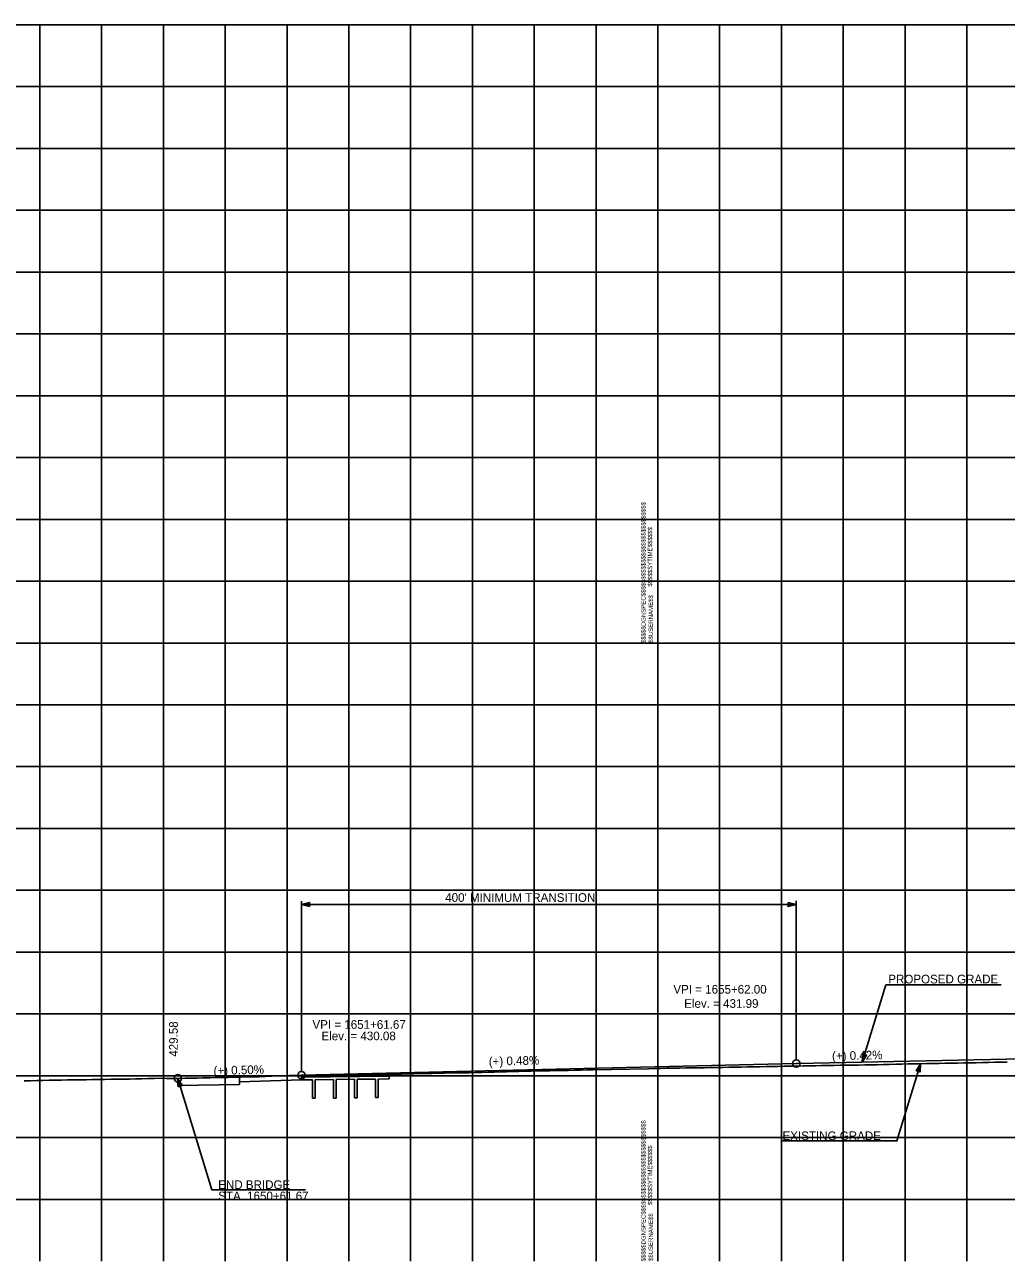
# Model space of a CAD drawing. Extents: x -90830 to 2015517, y -20856 to 836331.
# Drawn here: x 53861 to 54655, y -9797 to -8797 of the extents above; entities that cross this region are included whole.
import ezdxf

# ---------------------------------------------------------------- set-up
doc = ezdxf.new("R2010")
doc.units = 0
for name, color, linetype in [('Level 1', 7, 'Continuous'), ('RD_DDB_GradeTX', 7, 'Continuous'), ('RD_DDB_Profile_EX', 7, 'Continuous'), ('RD_DDB_Profile_Lbl', 7, 'Continuous'), ('RD_DDB_Profile_PR', 7, 'Continuous'), ('RD_DDB_VCLbl', 7, 'Continuous'), ('RD_PD_Final_TX', 7, 'Continuous')]:
    doc.layers.add(name, color=color, linetype=linetype)

msp = doc.modelspace()

# ---------------------------------------------------------------- linework, layer by layer
at = {"layer": 'Level 1'}
for p, q in [((52773.46, -8797.12), (54373.46, -8797.12)), ((53873.46, -8797.12), (53873.46, -9297.12)), ((53923.46, -8797.12), (53923.46, -9297.12)), ((53973.46, -8797.12), (53973.46, -9297.12)), ((54023.46, -8797.12), (54023.46, -9297.12)), ((54073.46, -8797.12), (54073.46, -9297.12)), ((54123.46, -8797.12), (54123.46, -9297.12)), ((54173.46, -8797.12), (54173.46, -9297.12)), ((54223.46, -8797.12), (54223.46, -9297.12)), ((54273.46, -8797.12), (54273.46, -9297.12)), ((54323.46, -8797.12), (54323.46, -9297.12)), ((54373.46, -8797.12), (54373.46, -9297.12)), ((54373.46, -8797.12), (54373.46, -9297.12)), ((54373.46, -8797.12), (55973.46, -8797.12)), ((54373.46, -8797.12), (54373.46, -9297.12)), ((54423.46, -8797.12), (54423.46, -9297.12)), ((54473.46, -8797.12), (54473.46, -9297.12)), ((54523.46, -8797.12), (54523.46, -9297.12)), ((54573.46, -8797.12), (54573.46, -9297.12)), ((54623.46, -8797.12), (54623.46, -9297.12)), ((52773.46, -8847.12), (54373.46, -8847.12)), ((54373.46, -8847.12), (55973.46, -8847.12)), ((52773.46, -8897.12), (54373.46, -8897.12)), ((54373.46, -8897.12), (55973.46, -8897.12)), ((52773.46, -8947.12), (54373.46, -8947.12)), ((54373.46, -8947.12), (55973.46, -8947.12)), ((52773.46, -8997.12), (54373.46, -8997.12)), ((54373.46, -8997.12), (55973.46, -8997.12)), ((52773.46, -9047.12), (54373.46, -9047.12)), ((54373.46, -9047.12), (55973.46, -9047.12)), ((52773.46, -9097.12), (54373.46, -9097.12)), ((54373.46, -9097.12), (55973.46, -9097.12)), ((52773.46, -9147.12), (54373.46, -9147.12)), ((54373.46, -9147.12), (55973.46, -9147.12)), ((52773.46, -9197.12), (54373.46, -9197.12)), ((54373.46, -9197.12), (55973.46, -9197.12)), ((52773.46, -9247.12), (54373.46, -9247.12)), ((54373.46, -9247.12), (55973.46, -9247.12)), ((52773.46, -9297.12), (54373.46, -9297.12)), ((52773.46, -9297.12), (54373.46, -9297.12)), ((53873.46, -9297.12), (53873.46, -9797.12)), ((53923.46, -9297.12), (53923.46, -9797.12)), ((53973.46, -9297.12), (53973.46, -9797.12)), ((54023.46, -9297.12), (54023.46, -9797.12)), ((54073.46, -9297.12), (54073.46, -9797.12)), ((54123.46, -9297.12), (54123.46, -9797.12)), ((54173.46, -9297.12), (54173.46, -9797.12)), ((54223.46, -9297.12), (54223.46, -9797.12)), ((54273.46, -9297.12), (54273.46, -9797.12)), ((54323.46, -9297.12), (54323.46, -9797.12)), ((54373.46, -9297.12), (54373.46, -9797.12)), ((54373.46, -9297.12), (54373.46, -9797.12)), ((54373.46, -9297.12), (55973.46, -9297.12)), ((54373.46, -9297.12), (55973.46, -9297.12)), ((54373.46, -9297.12), (54373.46, -9797.12)), ((54423.46, -9297.12), (54423.46, -9797.12)), ((54473.46, -9297.12), (54473.46, -9797.12)), ((54523.46, -9297.12), (54523.46, -9797.12)), ((54573.46, -9297.12), (54573.46, -9797.12)), ((54623.46, -9297.12), (54623.46, -9797.12)), ((52773.46, -9347.12), (54373.46, -9347.12)), ((54373.46, -9347.12), (55973.46, -9347.12)), ((52773.46, -9397.12), (54373.46, -9397.12)), ((54373.46, -9397.12), (55973.46, -9397.12)), ((52773.46, -9447.12), (54373.46, -9447.12)), ((54373.46, -9447.12), (55973.46, -9447.12)), ((52773.46, -9497.12), (54373.46, -9497.12)), ((54373.46, -9497.12), (55973.46, -9497.12)), ((52773.46, -9547.12), (54373.46, -9547.12)), ((54373.46, -9547.12), (55973.46, -9547.12)), ((52773.46, -9597.12), (54373.46, -9597.12)), ((54373.46, -9597.12), (55973.46, -9597.12)), ((52773.46, -9647.12), (54373.46, -9647.12)), ((54373.46, -9647.12), (55973.46, -9647.12)), ((52773.46, -9697.12), (54373.46, -9697.12)), ((54373.46, -9697.12), (55973.46, -9697.12)), ((52773.46, -9747.12), (54373.46, -9747.12)), ((54373.46, -9747.12), (55973.46, -9747.12))]:
    msp.add_line(p, q, dxfattribs=at)
at = {"layer": 'RD_DDB_GradeTX'}
for centre in [(54485.46, -9637.16), (53985.13, -9649.21), (54085.13, -9646.7)]:
    msp.add_circle(centre, 3, dxfattribs=at)
at = {"layer": 'RD_DDB_Profile_EX'}
for points in [[(54420.95, -9640.42), (54425.95, -9640.33), (54430.95, -9640.24), (54435.95, -9640.13), (54440.95, -9640.03), (54445.95, -9639.92), (54450.95, -9639.83), (54455.95, -9639.75), (54460.95, -9639.67), (54465.95, -9639.59), (54470.95, -9639.51), (54475.95, -9639.42), (54480.95, -9639.33), (54485.95, -9639.24), (54490.95, -9639.15), (54495.95, -9639.06), (54500.95, -9638.97), (54505.95, -9638.88), (54510.95, -9638.8), (54515.95, -9638.73), (54520.95, -9638.66), (54525.95, -9638.59), (54530.95, -9638.52), (54535.95, -9638.45), (54540.95, -9638.39), (54545.95, -9638.33), (54550.95, -9638.23), (54555.95, -9638.08), (54560.95, -9637.93), (54565.95, -9637.78), (54570.95, -9637.65), (54575.95, -9637.55), (54580.95, -9637.46), (54585.95, -9637.36), (54590.95, -9637.27), (54595.95, -9637.19), (54600.95, -9637.11), (54605.95, -9637.04), (54610.95, -9636.95), (54615.95, -9636.84), (54620.95, -9636.74), (54625.95, -9636.65), (54630.95, -9636.55), (54635.95, -9636.44), (54640.95, -9636.34), (54645.95, -9636.23), (54650.95, -9636.13), (54655.95, -9636.04)], [(53920.95, -9650.1), (53925.95, -9650.02), (53930.95, -9649.94), (53935.95, -9649.87), (53940.95, -9649.8), (53945.95, -9649.72), (53950.95, -9649.63), (53955.95, -9649.5), (53960.95, -9649.37), (53965.95, -9649.23), (53970.95, -9649.16), (53975.95, -9649.18), (53980.95, -9649.19), (53985.95, -9649.21), (53990.95, -9649.17), (53995.95, -9649.07), (54000.95, -9648.96), (54005.95, -9648.85), (54010.95, -9648.74), (54015.95, -9648.63), (54020.95, -9648.51), (54025.95, -9648.4), (54030.95, -9648.28), (54035.95, -9648.18), (54040.95, -9648.07), (54045.95, -9647.97), (54050.95, -9647.83), (54055.95, -9647.64), (54060.95, -9647.45), (54065.95, -9647.25), (54070.95, -9647.08), (54075.95, -9646.95), (54080.95, -9646.81), (54085.95, -9646.68), (54090.95, -9646.58), (54095.95, -9646.55), (54100.95, -9646.5), (54105.95, -9646.46), (54110.95, -9646.42), (54115.95, -9646.38), (54120.95, -9646.34), (54125.95, -9646.3), (54130.95, -9646.24), (54135.95, -9646.17), (54140.95, -9646.11), (54145.95, -9646.04), (54150.95, -9645.96), (54155.95, -9645.87), (54160.95, -9645.77), (54165.95, -9645.68), (54170.95, -9645.57), (54175.95, -9645.47), (54180.95, -9645.36), (54185.95, -9645.25), (54190.95, -9645.15), (54195.95, -9645.05), (54200.95, -9644.95), (54205.95, -9644.85), (54210.95, -9644.76), (54215.95, -9644.68), (54220.95, -9644.6), (54225.95, -9644.52), (54230.95, -9644.41), (54235.95, -9644.26), (54240.95, -9644.11), (54245.95, -9643.95), (54250.95, -9643.81), (54255.95, -9643.67), (54260.95, -9643.53), (54265.95, -9643.4), (54270.95, -9643.28), (54275.95, -9643.18), (54280.95, -9643.09), (54285.95, -9643), (54290.95, -9642.9), (54295.95, -9642.82), (54300.95, -9642.73), (54305.95, -9642.65), (54310.95, -9642.55), (54315.95, -9642.43), (54320.95, -9642.32), (54365.95, -9641.41), (54370.95, -9641.29), (54375.95, -9641.18), (54380.95, -9641.07), (54385.95, -9640.96), (54390.95, -9640.87), (54395.95, -9640.8), (54400.95, -9640.73), (54405.95, -9640.66), (54410.95, -9640.59), (54415.95, -9640.5), (54420.95, -9640.42)], [(53860.95, -9651.19), (53865.95, -9651.09), (53870.95, -9650.98), (53875.95, -9650.86), (53880.95, -9650.74), (53885.95, -9650.63), (53890.95, -9650.53), (53895.95, -9650.46), (53900.95, -9650.39), (53905.95, -9650.33), (53910.95, -9650.26), (53915.95, -9650.18), (53920.95, -9650.1)]]:
    msp.add_lwpolyline(points, dxfattribs=at)
at = {"layer": 'RD_DDB_Profile_PR'}
for p, q in [((54486.46, -9637.14), (54668.46, -9633.33)), ((53985.13, -9649.21), (54085.13, -9646.7))]:
    msp.add_line(p, q, dxfattribs=at)
msp.add_lwpolyline([(53985.13, -9649.21), (54085.13, -9646.7), (54485.46, -9637.16), (54486.46, -9637.14)], dxfattribs=at)
at = {"layer": 'RD_DDB_VCLbl'}
for p, q in [((54085.16, -9505.77), (54085.16, -9642.98)), ((54085.16, -9508.59), (54485.46, -9508.59)), ((54485.46, -9505.63), (54485.46, -9634.52))]:
    msp.add_line(p, q, dxfattribs=at)
at = {"layer": 'RD_PD_Final_TX'}
for p, q in [((54538.86, -9636.04), (54557.91, -9573.67)), ((54557.91, -9573.67), (54651.3, -9573.67)), ((54538.86, -9636.04), (54539.2, -9629.37)), ((54540.75, -9629.85), (54538.86, -9636.04)), ((54539.2, -9629.37), (54542.3, -9630.32)), ((54538.86, -9636.04), (54542.3, -9630.32)), ((54585.95, -9637.36), (54582.51, -9643.09)), ((54584.06, -9643.56), (54585.95, -9637.36)), ((54585.95, -9637.36), (54585.61, -9644.03)), ((53985.13, -9649.21), (53985.13, -9655.04)), ((54035.13, -9648.2), (54085.13, -9646.7)), ((54035.13, -9654.03), (54035.13, -9648.2)), ((54035.13, -9648.2), (54035.13, -9651.95)), ((54085.13, -9646.7), (54156.13, -9645.86)), ((54085.13, -9650.45), (54085.13, -9646.7)), ((54085.13, -9648.34), (54156.13, -9647.5)), ((54113.13, -9650.12), (54128.13, -9649.94)), ((54128.13, -9649.94), (54128.13, -9664.93)), ((54130.13, -9649.92), (54145.13, -9649.74)), ((54130.13, -9649.92), (54130.13, -9664.93)), ((54145.13, -9649.74), (54145.13, -9664.73)), ((54147.13, -9649.72), (54156.13, -9649.61)), ((54147.13, -9649.72), (54147.13, -9664.73)), ((54156.13, -9649.61), (54156.13, -9645.86)), ((54585.61, -9644.03), (54582.51, -9643.09)), ((53985.13, -9655.04), (54035.13, -9654.03)), ((54035.13, -9651.95), (54085.13, -9650.45)), ((54085.13, -9650.45), (54094.13, -9650.35)), ((54094.13, -9650.35), (54094.13, -9665.34)), ((54096.13, -9650.32), (54111.13, -9650.14)), ((54096.13, -9650.32), (54096.13, -9665.34)), ((54111.13, -9650.14), (54111.13, -9665.14)), ((54113.13, -9650.12), (54113.13, -9665.14)), ((54096.13, -9665.34), (54094.13, -9665.34)), ((54113.13, -9665.14), (54111.13, -9665.14)), ((54130.13, -9664.93), (54128.13, -9664.93)), ((54147.13, -9664.73), (54145.13, -9664.73))]:
    msp.add_line(p, q, dxfattribs=at)
for points in [[(54091.76, -9510.24), (54085.16, -9508.59), (54091.76, -9506.94)], [(54478.86, -9506.94), (54485.46, -9508.59), (54478.86, -9510.24)], [(53985.48, -9656), (53985.13, -9649.21), (53988.64, -9655.04)]]:
    msp.add_lwpolyline(points, close=True, dxfattribs=at)
for points in [[(54540.68, -9629.91), (54538.92, -9635.68), (54540.65, -9629.86), (54538.95, -9635.4), (54540.58, -9629.87), (54538.95, -9635.2), (54540.5, -9629.86), (54538.96, -9634.96), (54540.44, -9629.82), (54538.98, -9634.61), (54540.36, -9629.78), (54539.01, -9634.22), (54540.27, -9629.79), (54539.03, -9633.93), (54540.21, -9629.75), (54539.05, -9633.6), (54540.13, -9629.77), (54539.07, -9633.31), (54540.09, -9629.7), (54539.07, -9633.06), (54539.99, -9629.7), (54539.08, -9632.7), (54539.92, -9629.66), (54539.13, -9632.27), (54539.84, -9629.63), (54539.11, -9631.97), (54539.77, -9629.6), (54539.14, -9631.51), (54539.68, -9629.61), (54539.18, -9631.15), (54539.6, -9629.54), (54539.19, -9630.83), (54539.53, -9629.55), (54539.2, -9630.54), (54539.47, -9629.48), (54539.22, -9630.18), (54539.39, -9629.52), (54539.25, -9629.78), (54539.3, -9629.52)], [(54539.02, -9635.66), (54540.77, -9629.94), (54539.12, -9635.46), (54540.85, -9629.96), (54539.22, -9635.28), (54540.91, -9629.95), (54539.34, -9635.12), (54540.95, -9629.98), (54539.47, -9634.92), (54541.02, -9629.99), (54539.59, -9634.73), (54541.07, -9630), (54539.72, -9634.51), (54541.14, -9630.01), (54539.88, -9634.24), (54541.23, -9630.05), (54540.01, -9633.99), (54541.29, -9630.04), (54540.15, -9633.74), (54541.35, -9630.07), (54540.31, -9633.51), (54541.41, -9630.09), (54540.46, -9633.25), (54541.45, -9630.15), (54540.66, -9632.91), (54541.52, -9630.14), (54540.81, -9632.68), (54541.58, -9630.13), (54541, -9632.39), (54541.64, -9630.17), (54541.15, -9632.09), (54541.71, -9630.21), (54541.29, -9631.85), (54541.78, -9630.27), (54541.46, -9631.63), (54541.83, -9630.29), (54541.64, -9631.28), (54541.93, -9630.26), (54541.75, -9631.08), (54542.04, -9630.3), (54541.88, -9630.95), (54542.12, -9630.39), (54542.2, -9630.35), (54542.09, -9630.38)], [(54473.51, -9699.73), (54566.9, -9699.73), (54585.95, -9637.36)], [(54585.78, -9637.75), (54584.04, -9643.47), (54585.68, -9637.94), (54583.96, -9643.45), (54585.58, -9638.12), (54583.9, -9643.46), (54585.46, -9638.28), (54583.85, -9643.43), (54585.33, -9638.48), (54583.78, -9643.42), (54585.22, -9638.67), (54583.73, -9643.41), (54585.08, -9638.9), (54583.66, -9643.4), (54584.93, -9639.17), (54583.58, -9643.36), (54584.8, -9639.41), (54583.52, -9643.37), (54584.65, -9639.66), (54583.46, -9643.34), (54584.5, -9639.9), (54583.4, -9643.32), (54584.35, -9640.16), (54583.36, -9643.26), (54584.14, -9640.5), (54583.28, -9643.27), (54583.99, -9640.72), (54583.22, -9643.28), (54583.8, -9641.02), (54583.17, -9643.23), (54583.65, -9641.32), (54583.1, -9643.2), (54583.51, -9641.56), (54583.03, -9643.13), (54583.35, -9641.77), (54582.98, -9643.12), (54583.17, -9642.13), (54582.87, -9643.14), (54583.05, -9642.33), (54582.77, -9643.11), (54582.93, -9642.46), (54582.69, -9643.02), (54582.6, -9643.06), (54582.71, -9643.02)], [(54584.12, -9643.5), (54585.89, -9637.73), (54584.15, -9643.55), (54585.86, -9638.01), (54584.22, -9643.54), (54585.85, -9638.21), (54584.3, -9643.55), (54585.85, -9638.44), (54584.36, -9643.58), (54585.83, -9638.8), (54584.45, -9643.62), (54585.79, -9639.18), (54584.54, -9643.62), (54585.77, -9639.47), (54584.6, -9643.65), (54585.76, -9639.8), (54584.67, -9643.64), (54585.74, -9640.09), (54584.72, -9643.71), (54585.73, -9640.34), (54584.82, -9643.71), (54585.72, -9640.7), (54584.89, -9643.74), (54585.67, -9641.14), (54584.96, -9643.78), (54585.69, -9641.44), (54585.04, -9643.8), (54585.67, -9641.89), (54585.12, -9643.8), (54585.62, -9642.26), (54585.2, -9643.87), (54585.61, -9642.58), (54585.27, -9643.86), (54585.61, -9642.87), (54585.34, -9643.92), (54585.58, -9643.23), (54585.42, -9643.89), (54585.56, -9643.63), (54585.5, -9643.89)], [(54088.35, -9739.38), (54012.68, -9739.38), (53985.13, -9649.21)]]:
    msp.add_lwpolyline(points, dxfattribs=at)

# ---------------------------------------------------------------- texts
at = {"layer": 'Level 1'}
for s, p in [('$$$$$DGNSPEC$$$$$$$$$$$$$$$$$$$$$$$$$$$$', (54363.56, -9297.17)), ('$$$$$SYTIME$$$$$$', (54368.86, -9251.57)), ('$$USERNAME$$', (54369.46, -9297.02)), ('$$$$$DGNSPEC$$$$$$$$$$$$$$$$$$$$$$$$$$$$', (54363.56, -9797.17)), ('$$$$$SYTIME$$$$$$', (54368.86, -9751.57)), ('$$USERNAME$$', (54369.46, -9797.02))]:
    msp.add_text(s, height=3.5436, rotation=90, dxfattribs=at).set_placement(p)
at = {"layer": 'RD_DDB_GradeTX'}
for s, rotation, p in [('(+) 0.42%', 1.19944, (54514.41, -9634.56)), ('(+) 0.50%', 1.43453, (54014.1, -9646.48)), ('(+) 0.50%', 1.43453, (54014.1, -9646.48)), ('(+) 0.48%', 1.36493, (54236.75, -9638.98))]:
    msp.add_text(s, height=7, rotation=rotation, dxfattribs=at).set_placement(p)
at = {"layer": 'RD_DDB_Profile_Lbl'}
for s, p in [('VPI = 1655+62.00', (54386.01, -9580.66)), ('Elev. = 431.99', (54394.78, -9592.16)), ('VPI = 1651+61.67', (54094.06, -9609.12)), ('Elev. = 430.08', (54101.36, -9618.39))]:
    msp.add_text(s, height=7, dxfattribs=at).set_placement(p)
msp.add_text('429.58', height=7, rotation=90, dxfattribs=at).set_placement((53985.13, -9631.71))
at = {"layer": 'RD_DDB_VCLbl'}
msp.add_text("400' MINIMUM TRANSITION", height=7, dxfattribs=at).set_placement((54201.45, -9506.46))
at = {"layer": 'RD_PD_Final_TX'}
for s, p in [('PROPOSED GRADE', (54559.86, -9572.42)), ('EXISTING GRADE', (54474.33, -9699.13)), ('END BRIDGE', (54017.81, -9738.68)), ('STA. 1650+61.67', (54017.81, -9747.78))]:
    msp.add_text(s, height=7, dxfattribs=at).set_placement(p)

doc.saveas('drawing.dxf')
